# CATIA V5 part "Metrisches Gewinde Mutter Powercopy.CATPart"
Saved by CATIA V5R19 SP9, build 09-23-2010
Part number: Metrisches Gewinde
Bounding box of the stored display mesh (mm): x -6.5 to 6.5, y -7.506 to 7.506, z 0 to 6.5
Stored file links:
  E:\Markus\CATIA\_Standards\Metrisches Gewinde Mutter Powercopy.CATPart
  E:\Markus\CATIA\_Standards\Metrisches Gewinde.txt
  Unbenannt-M8x20-Gewindestange.CATPart
  d:\Program Files\Dassault Systemes\B19\win_b64\reffiles\standard\MetricThickPitch.txt
  E:\Markus\CATIA\_Standards\Metrisches Gewinde 2.CATPart

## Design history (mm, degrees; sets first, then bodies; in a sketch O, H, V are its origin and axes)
Set1 "Eingaben"
  Point1 "Punkt MitteGewinde": (0, 0, 0)
Set2 "MetrischesGewinde_mit_Bohrung"
  Plane1 "EbeneSenkrechtZurAchse": type Offset, RefPlane end face of Pad1, Offset 0
  Line1 "GewindeAchse": type PtDir, RefPoint Sketch4, Direction Plane1, Start 0, End 5 {= Hole1.ThreadingDepth}
  Line2 "LinieSkizzenEbene": stored without definition
  Plane2 "SkizzenEbene": type 2Lines, Element1 Line1, Element2 Line2
  Line3 "LinieStartHelix": type Angle, RefPoint Sketch4, Curve Line1, Support Plane2, Start 0, End 4, Angle 90
  Point2 "StartpunktHelix": type OnCurve, Support Line3, Ratio 1
  Helix1 "HelixGewinde": Direction Line1, RefPoint Point2, Pitch 1.25 {= Hole1.Pas}, Height 6.25 {= Hole1.ThreadingDepth  +Hole1.Pas}, TaperAngle 0
  Sketch1 "GewindeSkizze" on Plane2, origin (0, 0, 6.5), H (0, 1, 0), V (0, 0, -1)
    line L1 (5, 0.625) -> (4.0451, 0.625)
    arc A1 centre (3.4136, 0) radius 0.1804 from (3.3234, 0.1562) to (3.3234, -0.1562) ccw
    point P3 (3.4136, 0)
    line L2 (3.3234, -0.1562) -> (4, -0.5469)
    line L3 (5, -0.625) -> (5, 0.625)
    line L4 (4, 0.5469) -> (3.3234, 0.1562)
    line L5 (4.0451, -0.625) -> (5, -0.625)
    arc A2 centre (3.9549, 0.625) radius 0.0902 from (4, 0.5469) to (4.0451, 0.625) ccw
    point P6 (4, 0.5469)
    point P7 (3.9549, 0.625)
    arc A3 centre (3.9549, -0.625) radius 0.0902 from (4.0451, -0.625) to (4, -0.5469) ccw
    point P9 (3.9549, -0.625)
    construction line L6 (3.9549, 0.625) -> (3.9549, -0.625)
    angle L2 L4 = 60
    length L3 = 1.25 {= Hole1.Pas}
    radius A1 = 0.1804 {= 0.1443*Hole1.Pas}
    distance A1 V = 3.2332 {= (Hole1.DiameterThread  -1.2269*Hole1.Pas )/2+Set2.GewindeOffset}
    radius A2 = 0.0902 (reference)
    radius A3 = 0.0902 (reference)
    distance V P6 = 4 {= Hole1.DiameterThread /2+Set2.GewindeOffset}
    length L1 = 0.9549
    tangency: A1 L4, L2 A1, A2 L4, A3 L2
    vertical: L3 V, L6 V
    coincidence: P3 H, P7 L1, P9 L5
    symmetry: L4 L2 H, L1 L5 H
    horizontal: L5 H, L1 H
  Extract1: ExtractElem Sketch1.A2
  Extract2: ExtractElem Sketch1.L4
  Extract3: ExtractElem Sketch1.A1
  Join1: Elements (Extract3; Extract1; Extract2)
  Extract4: ExtractElem Sketch1.L2
  Extract5: ExtractElem Sketch1.A3
  Join2: Elements (Extract4; Extract5)
  Sweep1: type Unspec, Profile Join1, Guide Helix1, AngleRef 0, PullingDir Line1
  Sweep2: type Unspec, Profile Join2, Guide Helix1, AngleRef 0, PullingDir Line1
  Trim1 "Gewindedurchgangsloch": Trimmed (Sweep1; Sweep2)
  Point3 "EndeGewinde": type OnCurve, Support Line1, Ratio 1
  Sketch2 "SkizzePhase" on Plane2, origin (0, 0, 1.5), H (0, 1, 0), V (0, 0, 1)
    line L1 (4.1804, 0.4947) -> (0, -1.9188)
    point P1 (4.1804, 0.4947)
    point P2 (0, -1.9188)
    point P3 (3.3235, 0)
    distance V P1 = 4.1804 {= Hole1.DiameterThread /2 + 0.1443*Hole1.Pas +Set2.GewindeOffset}
    angle L1 H = 30 {= 30deg *List(PhaseAmGewindeauslauf )->IndexOf(true,0)}
    distance P3 V = 3.3235 {= Hole1.Diameter /2}
    coincidence: P2 V, P3 L1, P3 H
  Revol1: Element1 Sketch2, Line Line1, Angle1 360
  Trim2 "GewindeMitPhase": Trimmed (Trim1; Revol1)
  DatumSurface1
Body1 (main body)
  Sketch3 on xy-plane, origin (0, 0, 0), H (1, 0, 0), V (0, 1, 0)
    point P1 (6.5, -3.7528)
    point P2 (6.5, 3.7528)
    point P3 (0, 7.5056)
    point P4 (-6.5, 3.7528)
    point P5 (-6.5, -3.7528)
    point P6 (0, -7.5056)
    point P7 (6.5, 0)
    line L1 (6.5, -3.7528) -> (6.5, 3.7528)
    line L2 (6.5, 3.7528) -> (0, 7.5056)
    line L3 (0, 7.5056) -> (-6.5, 3.7528)
    line L4 (-6.5, 3.7528) -> (-6.5, -3.7528)
    line L5 (-6.5, -3.7528) -> (0, -7.5056)
    line L6 (0, -7.5056) -> (6.5, -3.7528)
    construction line L7 (0, 0) -> (6.5, 0)
    construction circle A1 centre (0, 0) radius 7.5056
    construction arc A2 centre (-6.5, -3.7528) radius 7.5056 from (-6.5, 3.7528) to (0, -7.5056) cw
    construction arc A3 centre (6.5, 3.7528) radius 7.5056 from (0, 7.5056) to (6.5, -3.7528) ccw
    distance L1 L4 = 13
    horizontal: L7 H
    coincidence: A1 P1, A1 P2, A1 P3, A1 P4, A1 P5, A1 P6, A2 O, A3 O
    midpoint: P7 L1
    parallelism: L1 L4
  Pad1: profile Sketch3, direction (0, 0, 1), length 6.5
  Sketch4 on Plane1, origin (2.0976, -0.9361, 6.5), H (1, 0, 0), V (0, -1, 0)
    point P1 (-2.0976, -0.9361)
    reference projected point E1 (-2.0976, -0.9361) from Point1
    coincidence: P1 E1
  Hole1 "Bohrung": placed by Sketch4, at (0, 0, 6.5) direction (0, 0, -1), diameter 6.647, depth 10, V-bottom angle 120, countersink depth 1.25, countersink angle 90, threaded "M8", thread diameter 8, thread depth 5, pitch 1.25
  Split1 "TrennenGewinde": SplitPlane DatumSurface1
Relations
  Line2 = line(Sketch4 ,direction(List(int(mod(angle(Plane1 ,direction(0mm,1mm,0mm) )/1deg ,180)) )->IndexOf(0,0)*10mm ,mod(angle(Plane1 ,direction(0mm,1mm,0mm) )/1deg ,180)*10mm ,0mm) ,0mm,10mm,true)
  DatumSurface1 = List(Trim2 , symmetry(Trim2  ,Plane2 )  ) ->GetItem( 1 +List(Linksgewinde )->IndexOf(true,0)  )
  Linksgewinde = Hole1.TapSide == "Left_Threaded"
